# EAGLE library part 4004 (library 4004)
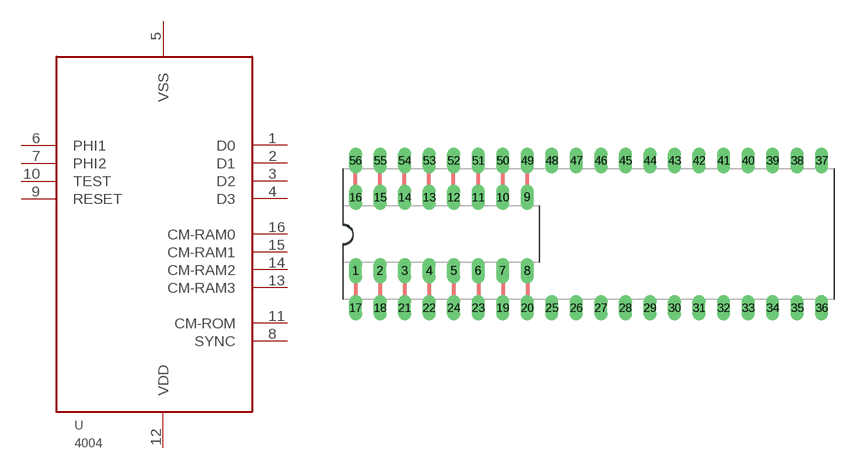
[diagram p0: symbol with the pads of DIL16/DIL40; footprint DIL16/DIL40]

Designator prefix -

## 4004  [DIL16/DIL40]
1  D0
2  D1
3  D2
4  D3
5  VSS
6  PHI1
7  PHI2
8  SYNC
9  RESET
10  TEST
11  CM-ROM
12  VDD
13  CM-RAM3
14  CM-RAM2
15  CM-RAM1
16  CM-RAM0

## Footprint DIL16/DIL40 (pad centres in mm)
Dual In Line Package
drill 0.813 long: 1 -8.89,-3.81; 2 -6.35,-3.81; 3 -3.81,-3.81; 4 -1.27,-3.81; 5 1.27,-3.81; 6 3.81,-3.81; 7 6.35,-3.81; 8 8.89,-3.81; 9 8.89,3.81; 10 6.35,3.81; 11 3.81,3.81; 12 1.27,3.81; 13 -1.27,3.81; 14 -3.81,3.81; 15 -6.35,3.81; 16 -8.89,3.81; 17 -8.89,-7.62; 18 -6.35,-7.62; 19 6.35,-7.62; 20 8.89,-7.62; 21 -3.81,-7.62; 22 -1.27,-7.62; 23 3.81,-7.62; 24 1.27,-7.62; 25 11.43,-7.62; 26 13.97,-7.62; 27 16.51,-7.62; 28 19.05,-7.62; 29 21.59,-7.62; 30 24.13,-7.62; 31 26.67,-7.62; 32 29.21,-7.62; 33 31.75,-7.62; 34 34.29,-7.62; 35 36.83,-7.62; 36 39.37,-7.62; 37 39.37,7.62; 38 36.83,7.62; 39 34.29,7.62; 40 31.75,7.62; 41 29.21,7.62; 42 26.67,7.62; 43 24.13,7.62; 44 21.59,7.62; 45 19.05,7.62; 46 16.51,7.62; 47 13.97,7.62; 48 11.43,7.62; 49 8.89,7.62; 50 6.35,7.62; 51 3.81,7.62; 52 1.27,7.62; 53 -1.27,7.62; 54 -3.81,7.62; 55 -6.35,7.62; 56 -8.89,7.62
